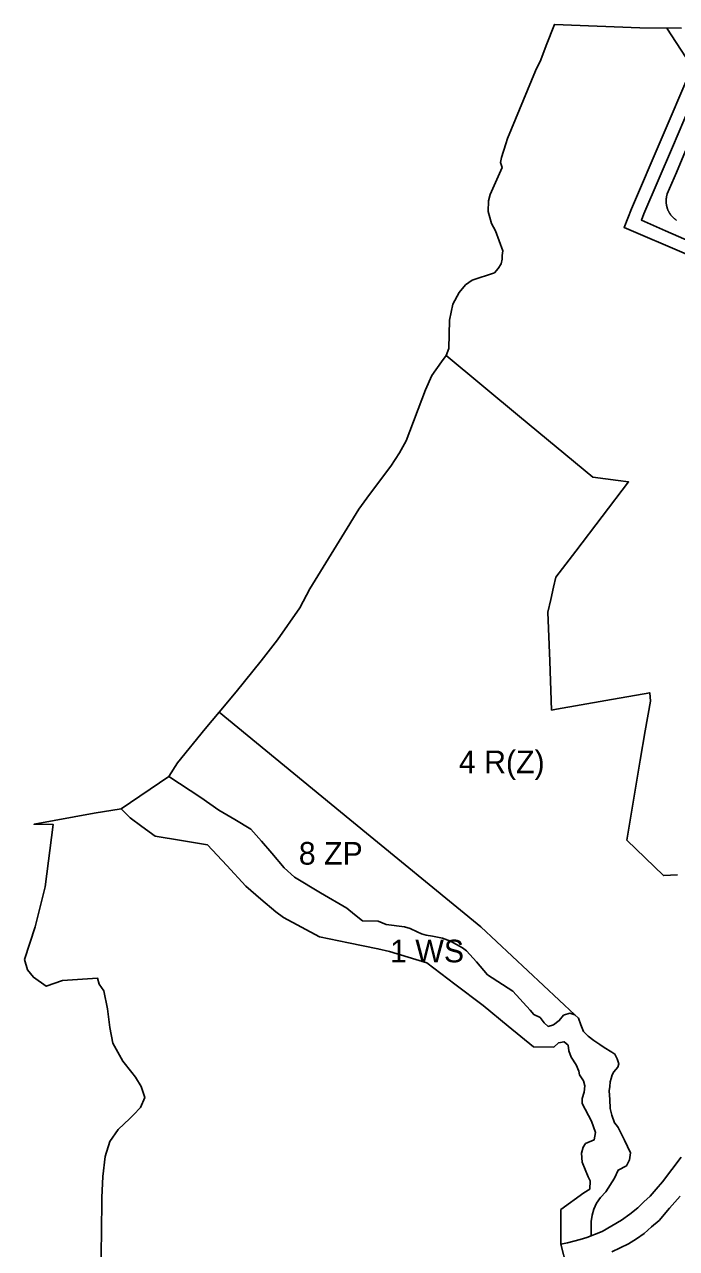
# Model space of a CAD drawing. Extents: x 7423432 to 7425824, y 5537848 to 5539677.
# Drawn here: x 7423432 to 7423720, y 5538420 to 5538961 of the extents above; entities that cross this region are included whole.
import ezdxf

# ---------------------------------------------------------------- set-up
doc = ezdxf.new("R2010")
doc.units = 0
for name, color, linetype in [('linie_rozgraniczajace', 7, 'Continuous'), ('linie_zabudowy_nieprzekraczalne', 7, 'Continuous'), ('oznaczenia_przeznaczen', 7, 'Continuous')]:
    doc.layers.add(name, color=color, linetype=linetype)

msp = doc.modelspace()

# ---------------------------------------------------------------- linework, layer by layer
at = {"layer": 'linie_rozgraniczajace'}
for points in [[(7423617.91, 5538815.04), (7423618.97, 5538818.19), (7423619.29, 5538830.65), (7423620.74, 5538837.66), (7423623.63, 5538842.93), (7423626.43, 5538846.3), (7423629.39, 5538848.27), (7423639.18, 5538851.58), (7423640.75, 5538853.49), (7423642.1, 5538855.54), (7423642.54, 5538857.61), (7423642.65, 5538859.23), (7423642.85, 5538861.27), (7423639.57, 5538870.1), (7423637.9, 5538873.35), (7423636.37, 5538878.72), (7423636.58, 5538883.4), (7423637.35, 5538886.1), (7423642.63, 5538898.03), (7423641.91, 5538900.35), (7423642.27, 5538902.44), (7423644.23, 5538908.52), (7423644.9, 5538910.84), (7423657.36, 5538940.76), (7423659.67, 5538945.59), (7423662.09, 5538951.94), (7423665.67, 5538961.28), (7423703.32, 5538959.73), (7423721.75, 5538959.68)], [(7423727.87, 5538930.65), (7423717.78, 5538907.05), (7423705.19, 5538877.61), (7423704.1, 5538874.83), (7423709.43, 5538872.51), (7423714.77, 5538870.18), (7423728.57, 5538864.14)], [(7423704.1, 5538874.83), (7423705.19, 5538877.61), (7423717.78, 5538907.05), (7423727.87, 5538930.65)], [(7423715.02, 5538882.83), (7423715.01, 5538883.03), (7423715.01, 5538883.23), (7423715.01, 5538883.43), (7423715.02, 5538883.64), (7423715.02, 5538883.84), (7423715.04, 5538884.04), (7423715.06, 5538884.24), (7423715.08, 5538884.44), (7423715.1, 5538884.64), (7423715.13, 5538884.84), (7423715.16, 5538885.04), (7423715.2, 5538885.24), (7423715.24, 5538885.43), (7423715.29, 5538885.63), (7423715.33, 5538885.83), (7423715.39, 5538886.02), (7423715.44, 5538886.21), (7423715.5, 5538886.41), (7423719.57, 5538895.95), (7423723.63, 5538905.49)], [(7423723.63, 5538905.49), (7423719.57, 5538895.95), (7423715.5, 5538886.41), (7423715.44, 5538886.21), (7423715.39, 5538886.02), (7423715.33, 5538885.83), (7423715.29, 5538885.63), (7423715.24, 5538885.43), (7423715.2, 5538885.24), (7423715.16, 5538885.04), (7423715.13, 5538884.84), (7423715.1, 5538884.64), (7423715.08, 5538884.44), (7423715.06, 5538884.24), (7423715.04, 5538884.04), (7423715.02, 5538883.84), (7423715.02, 5538883.64), (7423715.01, 5538883.43), (7423715.01, 5538883.23), (7423715.01, 5538883.03), (7423715.02, 5538882.83), (7423715.03, 5538882.63), (7423715.05, 5538882.43), (7423715.07, 5538882.23), (7423715.09, 5538882.03), (7423715.11, 5538881.83), (7423715.15, 5538881.63), (7423715.18, 5538881.43), (7423715.22, 5538881.23), (7423715.26, 5538881.03), (7423715.31, 5538880.84), (7423715.36, 5538880.64), (7423715.41, 5538880.45), (7423715.47, 5538880.26), (7423715.53, 5538880.06), (7423715.6, 5538879.87), (7423715.67, 5538879.68), (7423715.74, 5538879.5), (7423715.82, 5538879.31), (7423715.9, 5538879.12), (7423715.98, 5538878.94), (7423716.07, 5538878.76), (7423716.16, 5538878.58), (7423716.26, 5538878.4), (7423716.36, 5538878.23), (7423716.46, 5538878.05), (7423716.56, 5538877.88), (7423716.67, 5538877.71), (7423716.78, 5538877.54), (7423716.9, 5538877.38), (7423717.02, 5538877.22), (7423717.14, 5538877.06), (7423717.26, 5538876.9), (7423717.39, 5538876.74), (7423717.52, 5538876.59), (7423717.66, 5538876.44), (7423717.8, 5538876.29), (7423717.94, 5538876.15), (7423718.08, 5538876), (7423718.22, 5538875.86), (7423718.37, 5538875.73), (7423718.52, 5538875.59), (7423718.68, 5538875.46), (7423718.83, 5538875.34), (7423718.99, 5538875.21), (7423719.15, 5538875.09), (7423719.32, 5538874.97), (7423719.48, 5538874.86), (7423719.65, 5538874.75)], [(7423716.07, 5538878.76), (7423715.98, 5538878.94), (7423715.9, 5538879.12), (7423715.82, 5538879.31), (7423715.74, 5538879.5), (7423715.67, 5538879.68), (7423715.6, 5538879.87), (7423715.53, 5538880.06), (7423715.47, 5538880.26), (7423715.41, 5538880.45), (7423715.36, 5538880.64), (7423715.31, 5538880.84), (7423715.26, 5538881.03), (7423715.22, 5538881.23), (7423715.18, 5538881.43), (7423715.15, 5538881.63), (7423715.11, 5538881.83), (7423715.09, 5538882.03), (7423715.07, 5538882.23), (7423715.05, 5538882.43), (7423715.03, 5538882.63), (7423715.02, 5538882.83)], [(7423719.65, 5538874.75), (7423719.48, 5538874.86), (7423719.32, 5538874.97), (7423719.15, 5538875.09), (7423718.99, 5538875.21), (7423718.83, 5538875.34), (7423718.68, 5538875.46), (7423718.52, 5538875.59), (7423718.37, 5538875.73), (7423718.22, 5538875.86), (7423718.08, 5538876), (7423717.94, 5538876.15), (7423717.8, 5538876.29), (7423717.66, 5538876.44), (7423717.52, 5538876.59), (7423717.39, 5538876.74), (7423717.26, 5538876.9), (7423717.14, 5538877.06), (7423717.02, 5538877.22), (7423716.9, 5538877.38), (7423716.78, 5538877.54), (7423716.67, 5538877.71), (7423716.56, 5538877.88), (7423716.46, 5538878.05), (7423716.36, 5538878.23), (7423716.26, 5538878.4), (7423716.16, 5538878.58), (7423716.07, 5538878.76)], [(7423728.57, 5538864.14), (7423714.77, 5538870.18), (7423709.43, 5538872.51), (7423704.1, 5538874.83)], [(7423517.62, 5538657.49), (7423525.13, 5538666.44), (7423536.2, 5538680.2), (7423543.28, 5538689.35), (7423553.26, 5538703.49), (7423557.7, 5538711.89), (7423571.73, 5538734.97), (7423579.27, 5538747.2), (7423583.96, 5538753.68), (7423593.39, 5538766.2), (7423597.29, 5538771.99), (7423600.14, 5538777.33), (7423608.68, 5538799.88), (7423611.57, 5538806.12), (7423615.75, 5538812.17), (7423617.91, 5538815.04), (7423650.29, 5538788.15), (7423682.67, 5538761.27), (7423688.23, 5538760.52), (7423693.79, 5538759.78), (7423698.43, 5538759.16), (7423686.74, 5538743.89), (7423675.05, 5538728.61), (7423670.65, 5538722.86), (7423666.25, 5538717.12), (7423665.27, 5538712.72), (7423664.02, 5538707.19), (7423662.78, 5538701.66), (7423663.58, 5538680.02), (7423664.38, 5538658.37), (7423666.61, 5538658.77), (7423688.31, 5538662.59), (7423707.77, 5538666.03), (7423708.06, 5538662.25), (7423705.78, 5538649.25), (7423703.51, 5538636.24), (7423700.58, 5538618.58), (7423697.66, 5538600.92), (7423705.72, 5538593.1), (7423713.79, 5538585.28), (7423720.05, 5538585.62)], [(7423720.05, 5538585.62), (7423713.79, 5538585.28), (7423705.72, 5538593.1), (7423697.66, 5538600.92), (7423700.58, 5538618.58), (7423703.51, 5538636.24), (7423705.78, 5538649.25), (7423708.06, 5538662.25), (7423707.77, 5538666.03), (7423688.31, 5538662.59), (7423666.61, 5538658.77), (7423664.38, 5538658.37), (7423663.58, 5538680.02), (7423662.78, 5538701.66), (7423664.02, 5538707.19), (7423665.27, 5538712.72), (7423666.25, 5538717.12), (7423670.65, 5538722.86), (7423675.05, 5538728.61), (7423686.74, 5538743.89), (7423698.43, 5538759.16), (7423693.79, 5538759.78), (7423688.23, 5538760.52), (7423682.67, 5538761.27), (7423650.29, 5538788.15), (7423617.91, 5538815.04)], [(7423693.36, 5538504.29), (7423693.1, 5538504.9), (7423692.85, 5538505.5), (7423692.38, 5538506.36), (7423690.98, 5538507.24), (7423687.65, 5538509.33), (7423685.69, 5538510.57), (7423683.12, 5538512.45), (7423680.53, 5538514.35), (7423678.52, 5538516.3), (7423677.4, 5538519.24), (7423676.28, 5538522.18), (7423674.63, 5538523.73), (7423653.86, 5538543.13), (7423633.1, 5538562.53), (7423575.36, 5538610.01), (7423517.62, 5538657.49)], [(7423474.28, 5538614.8), (7423495.33, 5538628.97), (7423495.34, 5538628.97), (7423509.52, 5538619.76), (7423517.44, 5538614.19), (7423524.54, 5538609.99), (7423531.64, 5538605.79), (7423536.23, 5538600.45), (7423540.81, 5538595.1), (7423546.34, 5538588.71), (7423550.83, 5538584.48), (7423562.37, 5538577.68), (7423573.91, 5538570.89), (7423577.42, 5538568.07), (7423580.94, 5538565.25), (7423587.79, 5538565.04), (7423591.39, 5538563.67), (7423599.39, 5538562.53), (7423601.99, 5538561.82), (7423605.09, 5538560.39), (7423606.9, 5538559.56), (7423607.96, 5538559.22), (7423609.03, 5538558.89), (7423611.81, 5538558.48), (7423616.27, 5538557.54), (7423619.7, 5538556.33), (7423625.02, 5538553.38), (7423626.87, 5538552), (7423631.31, 5538547.19), (7423636.08, 5538541.41), (7423647.3, 5538534.2), (7423654.89, 5538525.78), (7423656.55, 5538523.82), (7423659.3, 5538522.52), (7423661.09, 5538520.17), (7423662.91, 5538518.57), (7423665.29, 5538519.25), (7423667.79, 5538521.18), (7423669.73, 5538523.63), (7423672.42, 5538524.49), (7423674.63, 5538523.73), (7423676.28, 5538522.18), (7423677.4, 5538519.24), (7423678.52, 5538516.3), (7423680.53, 5538514.35), (7423683.12, 5538512.45), (7423685.69, 5538510.57), (7423687.65, 5538509.33), (7423690.98, 5538507.24), (7423692.38, 5538506.36), (7423692.85, 5538505.5), (7423693.1, 5538504.9), (7423693.36, 5538504.29), (7423694.1, 5538502.06), (7423693.67, 5538500.55), (7423691.98, 5538498.61), (7423691.24, 5538497.25), (7423690.75, 5538495.65), (7423690.27, 5538494.06), (7423690.07, 5538492.13), (7423689.86, 5538490.2), (7423690.08, 5538486.25), (7423690.3, 5538482.3), (7423691.04, 5538479.32), (7423692.26, 5538476.07), (7423693.04, 5538474.99), (7423693.83, 5538473.91), (7423696.55, 5538468.33), (7423699.28, 5538462.75), (7423698.76, 5538459.6), (7423697.54, 5538457.02), (7423693.89, 5538455.16), (7423692.18, 5538451.5), (7423688.32, 5538445.52), (7423685.95, 5538443.01), (7423684.28, 5538440.52), (7423683.14, 5538437.85), (7423682.33, 5538435.16), (7423681.91, 5538432.36), (7423681.87, 5538426.1), (7423679.93, 5538425.34), (7423677.07, 5538424.5), (7423674.21, 5538423.66), (7423671.37, 5538423), (7423668.53, 5538422.35), (7423668.5, 5538437.7), (7423678.63, 5538445.04), (7423681.33, 5538446.73), (7423681.46, 5538450.32), (7423680.62, 5538452.13), (7423677.88, 5538458.67), (7423677.68, 5538462.55), (7423678.3, 5538465.28), (7423679.46, 5538466.91), (7423683.23, 5538468.52), (7423683.79, 5538471.68), (7423682.11, 5538476.71), (7423677.94, 5538484.59), (7423677.93, 5538486.77), (7423678.86, 5538489.56)], [(7423431.59, 5538548.18), (7423436.33, 5538562.59), (7423440.7, 5538580.33), (7423444.24, 5538607.86), (7423435.84, 5538607.92), (7423462.38, 5538612.86), (7423474.28, 5538614.8), (7423478.22, 5538610.82), (7423483.4, 5538606.94), (7423489.33, 5538602.61), (7423500.87, 5538600.73), (7423512.4, 5538598.84), (7423520.91, 5538589.67), (7423529.43, 5538580.5), (7423536.01, 5538574.86), (7423542.6, 5538569.22), (7423546.02, 5538566.66), (7423553.93, 5538562.46), (7423561.85, 5538558.25), (7423574.77, 5538555.6), (7423587.7, 5538552.95), (7423592.8, 5538551.76), (7423601.05, 5538549.21), (7423609.3, 5538546.66), (7423621.73, 5538537.23), (7423634.17, 5538527.8), (7423645.3, 5538518.72), (7423656.43, 5538509.65), (7423665.34, 5538509.48), (7423667.44, 5538511.31), (7423669.96, 5538511.82), (7423671.68, 5538510.31), (7423672.02, 5538507.89), (7423673.01, 5538504.96), (7423675.33, 5538501.62), (7423676.45, 5538498.87), (7423676.77, 5538497.23), (7423678.45, 5538494.53), (7423679.03, 5538492.41), (7423678.86, 5538489.56), (7423677.93, 5538486.77), (7423677.94, 5538484.59), (7423682.11, 5538476.71), (7423683.79, 5538471.68), (7423683.23, 5538468.52), (7423679.46, 5538466.91), (7423678.3, 5538465.28), (7423677.68, 5538462.55), (7423677.88, 5538458.67), (7423680.62, 5538452.13), (7423681.46, 5538450.32), (7423681.33, 5538446.73), (7423678.63, 5538445.04), (7423668.5, 5538437.7), (7423668.53, 5538422.35), (7423670.97, 5538412.61)], [(7423678.86, 5538489.56), (7423679.03, 5538492.41), (7423678.45, 5538494.53), (7423676.77, 5538497.23), (7423676.45, 5538498.87), (7423675.33, 5538501.62), (7423673.01, 5538504.96), (7423672.02, 5538507.89), (7423671.68, 5538510.31), (7423669.96, 5538511.82), (7423667.44, 5538511.31), (7423665.34, 5538509.48), (7423656.43, 5538509.65), (7423645.3, 5538518.72), (7423634.17, 5538527.8), (7423621.73, 5538537.23), (7423609.3, 5538546.66), (7423601.05, 5538549.21), (7423592.8, 5538551.76), (7423587.7, 5538552.95), (7423574.77, 5538555.6), (7423561.85, 5538558.25), (7423553.93, 5538562.46), (7423546.02, 5538566.66), (7423542.6, 5538569.22), (7423536.01, 5538574.86), (7423529.43, 5538580.5), (7423520.91, 5538589.67), (7423512.4, 5538598.84), (7423500.87, 5538600.73), (7423489.33, 5538602.61), (7423483.4, 5538606.94), (7423478.22, 5538610.82), (7423474.28, 5538614.8)], [(7423465.53, 5538416.46), (7423465.55, 5538430.05), (7423465.72, 5538439.83), (7423465.77, 5538443.05), (7423466.13, 5538452.29), (7423467.16, 5538461.09), (7423469.36, 5538467.76), (7423473.01, 5538473.07), (7423478.05, 5538477.89), (7423479.77, 5538479.6), (7423482.9, 5538482.71), (7423484.78, 5538487.16), (7423483.14, 5538492.02), (7423480.62, 5538496.25), (7423479.02, 5538498.26), (7423475.06, 5538503.19), (7423470.6, 5538511.16), (7423469.29, 5538518.1), (7423468.19, 5538526.34), (7423466.67, 5538534.38), (7423464.61, 5538537.3), (7423463.9, 5538539.89), (7423448.32, 5538538.94), (7423441.21, 5538536.32), (7423435.57, 5538540.31), (7423432.89, 5538543.62), (7423431.59, 5538548.18)], [(7423721.65, 5538460.83), (7423713.46, 5538449.88), (7423710.67, 5538446.77), (7423707.89, 5538443.65), (7423705.2, 5538441.07), (7423702.51, 5538438.49), (7423698.94, 5538435.71), (7423695.36, 5538432.93), (7423691.04, 5538430.48), (7423686.73, 5538428.03), (7423683.33, 5538426.68), (7423681.87, 5538426.1), (7423681.91, 5538432.36), (7423682.33, 5538435.16), (7423683.14, 5538437.85), (7423684.28, 5538440.52), (7423685.95, 5538443.01), (7423688.32, 5538445.52), (7423692.18, 5538451.5), (7423693.89, 5538455.16), (7423697.54, 5538457.02), (7423698.76, 5538459.6), (7423699.28, 5538462.75), (7423696.55, 5538468.33), (7423693.83, 5538473.91), (7423693.04, 5538474.99), (7423692.26, 5538476.07), (7423691.04, 5538479.32), (7423690.3, 5538482.3), (7423690.08, 5538486.25), (7423689.86, 5538490.2), (7423690.07, 5538492.13), (7423690.27, 5538494.06), (7423690.75, 5538495.65), (7423691.24, 5538497.25), (7423691.98, 5538498.61), (7423693.67, 5538500.55), (7423694.1, 5538502.06), (7423693.36, 5538504.29)], [(7423668.53, 5538422.35), (7423671.37, 5538423), (7423674.21, 5538423.66), (7423677.07, 5538424.5), (7423679.93, 5538425.34), (7423681.87, 5538426.1), (7423683.33, 5538426.68), (7423686.73, 5538428.03), (7423691.04, 5538430.48), (7423695.36, 5538432.93), (7423698.94, 5538435.71), (7423702.51, 5538438.49), (7423705.2, 5538441.07), (7423707.89, 5538443.65), (7423710.67, 5538446.77), (7423713.46, 5538449.88), (7423721.65, 5538460.83)], [(7423691.06, 5538418.99), (7423694.76, 5538420.74), (7423698.45, 5538422.49), (7423701.87, 5538424.79), (7423705.3, 5538427.09), (7423708.58, 5538430), (7423711.86, 5538432.91), (7423716.53, 5538438.23), (7423721.2, 5538443.54)], [(7423721.2, 5538443.54), (7423716.53, 5538438.23), (7423711.86, 5538432.91), (7423708.58, 5538430), (7423705.3, 5538427.09), (7423701.87, 5538424.79), (7423698.45, 5538422.49), (7423694.76, 5538420.74), (7423691.06, 5538418.99)], [(7423670.97, 5538412.61), (7423668.53, 5538422.35)]]:
    msp.add_lwpolyline(points, dxfattribs=at)
msp.add_lwpolyline([(7423495.34, 5538628.97), (7423499.17, 5538635.01), (7423511.44, 5538650.12), (7423517.62, 5538657.49), (7423575.36, 5538610.01), (7423633.1, 5538562.53), (7423653.86, 5538543.13), (7423674.63, 5538523.73), (7423672.42, 5538524.49), (7423669.73, 5538523.63), (7423667.79, 5538521.18), (7423665.29, 5538519.25), (7423662.91, 5538518.57), (7423661.09, 5538520.17), (7423659.3, 5538522.52), (7423656.55, 5538523.82), (7423654.89, 5538525.78), (7423647.3, 5538534.2), (7423636.08, 5538541.41), (7423631.31, 5538547.19), (7423626.87, 5538552), (7423625.02, 5538553.38), (7423619.7, 5538556.33), (7423616.27, 5538557.54), (7423611.81, 5538558.48), (7423609.03, 5538558.89), (7423607.96, 5538559.22), (7423606.9, 5538559.56), (7423605.09, 5538560.39), (7423601.99, 5538561.82), (7423599.39, 5538562.53), (7423591.39, 5538563.67), (7423587.79, 5538565.04), (7423580.94, 5538565.25), (7423577.42, 5538568.07), (7423573.91, 5538570.89), (7423562.37, 5538577.68), (7423550.83, 5538584.48), (7423546.34, 5538588.71), (7423540.81, 5538595.1), (7423536.23, 5538600.45), (7423531.64, 5538605.79), (7423524.54, 5538609.99), (7423517.44, 5538614.19), (7423509.52, 5538619.76)], close=True, dxfattribs=at)
at = {"layer": 'linie_zabudowy_nieprzekraczalne'}
for points in [[(7423725.86, 5538941.12), (7423725.76, 5538943.54), (7423715.34, 5538959.7)], [(7423724.03, 5538859.79), (7423696.4, 5538871.64), (7423699.64, 5538879.89), (7423725.86, 5538941.12)]]:
    msp.add_lwpolyline(points, dxfattribs=at)

# ---------------------------------------------------------------- texts
at = {"layer": 'oznaczenia_przeznaczen'}
for s, p in [('4 R(Z)', (7423623.46, 5538630.49)), ('8 ZP', (7423552.76, 5538590.08)), ('1 WS', (7423593.06, 5538546.9))]:
    msp.add_text(s, height=10, dxfattribs=at).set_placement(p)

doc.saveas('drawing.dxf')
